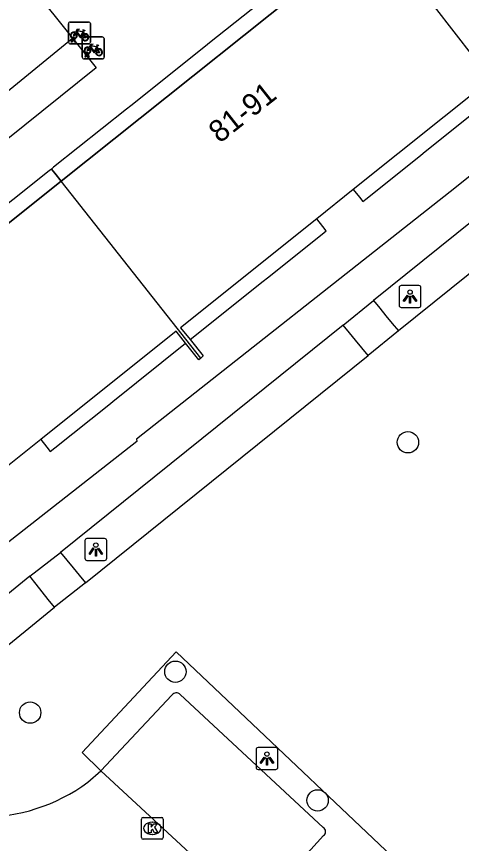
# Model space of a CAD drawing. Extents: x 159040 to 160094, y 381214 to 382518.
# Drawn here: x 159691.35 to 159711.7, y 381820.24 to 381858.06 of the extents above; entities that cross this region are included whole.
import ezdxf

# ---------------------------------------------------------------- set-up
doc = ezdxf.new("R2010")
doc.units = 0
for name, color, linetype in [('IMGEO_Boom', 7, 'Continuous'), ('IMGEO_Fietsenrek', 7, 'Continuous'), ('IMGEO_Haag', 7, 'Continuous'), ('IMGEO_Kolk', 7, 'Continuous'), ('IMGEO_Lichtpunt', 7, 'Continuous'), ('IMGEO_Pand', 7, 'Continuous'), ('IMGEO_Pand_nummerreeks', 7, 'Continuous'), ('IMGEO_Pand_overbouw', 7, 'Continuous'), ('IMGEO_Parkeervlak_open', 7, 'Continuous'), ('IMGEO_Rijbaan_lokaal_open', 7, 'Continuous'), ('IMGEO_Voetpad_gesloten', 7, 'Continuous'), ('IMGEO_Voetpad_open', 7, 'Continuous')]:
    doc.layers.add(name, color=color, linetype=linetype)

msp = doc.modelspace()

# ---------------------------------------------------------------- linework, layer by layer
at = {"layer": 'IMGEO_Boom'}
for centre in [(159709.248, 381838.586), (159698.615, 381828.091), (159691.971, 381826.221), (159705.119, 381822.205)]:
    msp.add_circle(centre, 0.489, dxfattribs=at)
at = {"layer": 'IMGEO_Fietsenrek'}
for p, q in [((159693.725, 381856.883), (159693.725, 381857.724)), ((159693.725, 381857.724), (159693.725, 381856.883)), ((159693.8, 381857.808), (159694.641, 381857.808)), ((159694.641, 381857.808), (159693.8, 381857.808)), ((159694.725, 381857.733), (159694.725, 381856.892)), ((159694.725, 381856.892), (159694.725, 381857.733)), ((159694.412, 381857.357), (159694.448, 381857.262)), ((159694.65, 381856.808), (159693.809, 381856.808)), ((159693.809, 381856.808), (159694.65, 381856.808)), ((159693.852, 381856.892), (159693.891, 381857.052)), ((159693.886, 381856.892), (159693.852, 381856.892)), ((159693.921, 381857.04), (159693.886, 381856.892)), ((159693.963, 381857.064), (159693.962, 381857.068)), ((159694.004, 381856.892), (159693.97, 381857.034)), ((159693.994, 381857.075), (159693.995, 381857.068)), ((159694.002, 381857.038), (159694.037, 381856.892)), ((159694.037, 381856.892), (159694.004, 381856.892)), ((159694.354, 381856.198), (159694.354, 381857.039)), ((159694.354, 381857.039), (159694.354, 381856.198)), ((159694.429, 381857.123), (159695.27, 381857.123)), ((159695.27, 381857.123), (159694.429, 381857.123)), ((159695.354, 381857.048), (159695.354, 381856.207)), ((159695.354, 381856.207), (159695.354, 381857.048)), ((159695.041, 381856.672), (159695.077, 381856.577)), ((159695.279, 381856.123), (159694.438, 381856.123)), ((159694.438, 381856.123), (159695.279, 381856.123)), ((159694.481, 381856.207), (159694.52, 381856.367)), ((159694.515, 381856.207), (159694.481, 381856.207)), ((159694.55, 381856.355), (159694.515, 381856.207)), ((159694.592, 381856.379), (159694.591, 381856.383)), ((159694.633, 381856.207), (159694.599, 381856.349)), ((159694.623, 381856.39), (159694.624, 381856.383)), ((159694.631, 381856.353), (159694.666, 381856.207)), ((159694.666, 381856.207), (159694.633, 381856.207))]:
    msp.add_line(p, q, dxfattribs=at)
for points in [[(159694.059, 381857.282), (159694.007, 381857.192), (159693.967, 381857.167), (159693.968, 381857.214), (159694.023, 381857.308)], [(159694.038, 381857.334), (159694.133, 381857.498), (159694.219, 381857.484), (159694.221, 381857.475), (159694.165, 381857.464), (159694.138, 381857.419), (159694.394, 381857.378)], [(159694.334, 381857.09), (159694.284, 381857.09), (159694.093, 381857.341), (159694.074, 381857.309)], [(159694.381, 381857.353), (159694.124, 381857.394), (159694.107, 381857.365), (159694.274, 381857.145), (159694.381, 381857.353)], [(159694.429, 381857.255), (159694.399, 381857.332), (159694.29, 381857.114), (159694.333, 381857.114)], [(159694.363, 381857.114), (159694.483, 381857.113), (159694.439, 381857.227)], [(159694.459, 381857.234), (159694.514, 381857.089), (159694.364, 381857.089)], [(159694.394, 381857.378), (159694.419, 381857.427), (159694.413, 381857.431), (159694.39, 381857.435), (159694.378, 381857.442), (159694.377, 381857.445), (159694.379, 381857.45), (159694.474, 381857.435), (159694.476, 381857.425), (159694.466, 381857.412), (159694.454, 381857.406), (159694.44, 381857.412), (159694.412, 381857.357)], [(159694.667, 381856.649), (159694.762, 381856.813), (159694.848, 381856.799), (159694.85, 381856.79), (159694.794, 381856.779), (159694.767, 381856.734), (159695.023, 381856.693)], [(159694.688, 381856.597), (159694.636, 381856.507), (159694.596, 381856.482), (159694.597, 381856.529), (159694.652, 381856.623)], [(159694.963, 381856.405), (159694.913, 381856.405), (159694.722, 381856.656), (159694.703, 381856.624)], [(159695.01, 381856.668), (159694.753, 381856.709), (159694.736, 381856.68), (159694.903, 381856.46), (159695.01, 381856.668)], [(159695.058, 381856.57), (159695.028, 381856.647), (159694.919, 381856.429), (159694.962, 381856.429)], [(159694.992, 381856.429), (159695.112, 381856.428), (159695.068, 381856.542)], [(159695.088, 381856.549), (159695.143, 381856.404), (159694.993, 381856.404)], [(159695.023, 381856.693), (159695.048, 381856.742), (159695.042, 381856.746), (159695.019, 381856.75), (159695.007, 381856.757), (159695.006, 381856.76), (159695.008, 381856.765), (159695.103, 381856.75), (159695.105, 381856.74), (159695.095, 381856.727), (159695.083, 381856.721), (159695.069, 381856.727), (159695.041, 381856.672)]]:
    msp.add_lwpolyline(points, dxfattribs=at)
for centre, radius, start, end in [((159693.803, 381857.73), 0.0779, 92.4484, 184.2845), ((159693.803, 381857.73), 0.0779, 92.4484, 184.2845), ((159694.647, 381857.73), 0.0779, 2.4484, 94.2845), ((159694.647, 381857.73), 0.0779, 2.4484, 94.2845), ((159693.965, 381857.193), 0.159, 62.6766, 242.1369), ((159693.965, 381857.193), 0.129, 63.3192, 238.903), ((159693.965, 381857.193), 0.129, 283.6043, 43.4302), ((159693.965, 381857.193), 0.159, 283.5766, 46.6042), ((159694.492, 381857.109), 0.159, 113.3408, 178.3217), ((159694.492, 381857.109), 0.159, 187.0065, 105.7708), ((159694.492, 381857.109), 0.129, 113.923, 177.9556), ((159694.492, 381857.109), 0.129, 188.6715, 104.5883), ((159693.803, 381856.886), 0.0779, 182.4484, 274.2845), ((159693.803, 381856.886), 0.0779, 182.4484, 274.2845), ((159693.945, 381857.064), 0.0499, 12.8025, 158.6934), ((159693.965, 381857.193), 0.159, 253.9967, 271.7867), ((159693.945, 381857.064), 0.0174, 12.8025, 163.4502), ((159693.965, 381857.193), 0.129, 253.415, 269.0204), ((159694.432, 381857.045), 0.0779, 92.4484, 184.2845), ((159694.432, 381857.045), 0.0779, 92.4484, 184.2845), ((159694.647, 381856.886), 0.0779, 272.4484, 4.2845), ((159694.647, 381856.886), 0.0779, 272.4484, 4.2845), ((159695.276, 381857.045), 0.0779, 2.4484, 94.2845), ((159695.276, 381857.045), 0.0779, 2.4484, 94.2845), ((159694.594, 381856.508), 0.159, 62.6766, 242.1369), ((159694.594, 381856.508), 0.129, 63.3192, 238.903), ((159694.574, 381856.379), 0.0499, 12.8025, 158.6934), ((159694.594, 381856.508), 0.129, 283.6043, 43.4302), ((159694.594, 381856.508), 0.159, 283.5766, 46.6042), ((159695.121, 381856.424), 0.159, 113.3408, 178.3217), ((159695.121, 381856.424), 0.159, 187.0065, 105.7708), ((159695.121, 381856.424), 0.129, 113.923, 177.9556), ((159695.121, 381856.424), 0.129, 188.6715, 104.5883), ((159694.432, 381856.201), 0.0779, 182.4484, 274.2845), ((159694.432, 381856.201), 0.0779, 182.4484, 274.2845), ((159694.594, 381856.508), 0.159, 253.9967, 271.7867), ((159694.574, 381856.379), 0.0174, 12.8025, 163.4502), ((159694.594, 381856.508), 0.129, 253.415, 269.0204), ((159695.276, 381856.201), 0.0779, 272.4484, 4.2845), ((159695.276, 381856.201), 0.0779, 272.4484, 4.2845)]:
    msp.add_arc(centre, radius, start, end, dxfattribs=at)
at = {"layer": 'IMGEO_Haag'}
for points in [[(159683.256, 381848.357), (159693.903, 381857.065)], [(159721.644, 381853.983), (159708.82, 381843.677)], [(159694.506, 381832.155), (159707.427, 381842.553)], [(159684.126, 381823.723), (159693.082, 381831.042)], [(159695.21, 381823.556), (159694.347, 381824.39), (159698.652, 381828.997), (159711.13, 381817.175)]]:
    msp.add_lwpolyline(points, dxfattribs=at)
at = {"layer": 'IMGEO_Kolk'}
for p, q in [((159697.06, 381820.502), (159697.06, 381821.354)), ((159697.135, 381821.428), (159697.987, 381821.428)), ((159698.061, 381821.354), (159698.061, 381820.502)), ((159697.548, 381821.208), (159697.573, 381821.208)), ((159697.571, 381820.648), (159697.546, 381820.648)), ((159697.987, 381820.428), (159697.135, 381820.428))]:
    msp.add_line(p, q, dxfattribs=at)
for points in [[(159697.06, 381820.502), (159697.06, 381821.354)], [(159697.135, 381821.428), (159697.987, 381821.428)], [(159698.061, 381821.354), (159698.061, 381820.502)], [(159697.381, 381821.128), (159697.504, 381821.128), (159697.504, 381820.977), (159697.634, 381821.128), (159697.798, 381821.128), (159697.652, 381820.977), (159697.805, 381820.728), (159697.653, 381820.728), (159697.568, 381820.892), (159697.504, 381820.825), (159697.504, 381820.728), (159697.381, 381820.728), (159697.381, 381821.128)], [(159697.987, 381820.428), (159697.135, 381820.428)]]:
    msp.add_lwpolyline(points, dxfattribs=at)
for centre, start, end in [((159697.137, 381821.352), 91.552, 178.448), ((159697.137, 381821.352), 91.552, 178.448), ((159697.985, 381821.352), 1.552, 88.448), ((159697.985, 381821.352), 1.552, 88.448), ((159697.137, 381820.504), 181.552, 268.448), ((159697.137, 381820.504), 181.552, 268.448), ((159697.985, 381820.504), 271.552, 358.448), ((159697.985, 381820.504), 271.552, 358.448)]:
    msp.add_arc(centre, 0.0765, start, end, dxfattribs=at)
for centre, major_axis, ratio, start_param, end_param in [((159697.547, 381820.928), (-0.387, 0.002), 0.722429, 4.712389, 7.853982), ((159697.572, 381820.928), (-0.39, 0.002), 0.717154, 1.570796, 4.712389)]:
    msp.add_ellipse(centre, major_axis=major_axis, ratio=ratio, start_param=start_param, end_param=end_param, dxfattribs=at)
at = {"layer": 'IMGEO_Lichtpunt'}
for p, q in [((159708.85, 381845.654), (159708.85, 381844.847)), ((159708.85, 381845.654), (159708.85, 381844.847)), ((159709.752, 381845.749), (159708.944, 381845.749)), ((159709.752, 381845.749), (159708.944, 381845.749)), ((159709.846, 381844.847), (159709.846, 381845.654)), ((159709.846, 381844.847), (159709.846, 381845.654)), ((159708.944, 381844.753), (159709.752, 381844.753)), ((159708.944, 381844.753), (159709.752, 381844.753)), ((159694.476, 381834.086), (159694.476, 381833.279)), ((159694.476, 381834.086), (159694.476, 381833.279)), ((159695.378, 381834.181), (159694.57, 381834.181)), ((159695.378, 381834.181), (159694.57, 381834.181)), ((159695.472, 381833.279), (159695.472, 381834.086)), ((159695.472, 381833.279), (159695.472, 381834.086)), ((159694.57, 381833.185), (159695.378, 381833.185)), ((159694.57, 381833.185), (159695.378, 381833.185)), ((159702.303, 381824.525), (159702.303, 381823.718)), ((159702.303, 381824.525), (159702.303, 381823.718)), ((159703.205, 381824.62), (159702.397, 381824.62)), ((159703.205, 381824.62), (159702.397, 381824.62)), ((159703.299, 381823.718), (159703.299, 381824.525)), ((159703.299, 381823.718), (159703.299, 381824.525)), ((159702.397, 381823.624), (159703.205, 381823.624)), ((159702.397, 381823.624), (159703.205, 381823.624))]:
    msp.add_line(p, q, dxfattribs=at)
for points in [[(159709.224, 381845.318), (159709.263, 381845.29), (159709.075, 381845.028), (159709.037, 381845.055), (159709.224, 381845.318)], [(159709.326, 381845.27), (159709.373, 381845.27), (159709.373, 381844.948), (159709.326, 381844.948), (159709.326, 381845.27)], [(159709.436, 381845.29), (159709.474, 381845.317), (159709.661, 381845.055), (159709.622, 381845.027), (159709.436, 381845.29)], [(159694.85, 381833.75), (159694.889, 381833.722), (159694.701, 381833.46), (159694.663, 381833.487), (159694.85, 381833.75)], [(159695.062, 381833.722), (159695.1, 381833.749), (159695.287, 381833.487), (159695.248, 381833.459), (159695.062, 381833.722)], [(159694.952, 381833.702), (159694.999, 381833.702), (159694.999, 381833.38), (159694.952, 381833.38), (159694.952, 381833.702)], [(159702.677, 381824.189), (159702.716, 381824.161), (159702.528, 381823.899), (159702.49, 381823.926), (159702.677, 381824.189)], [(159702.779, 381824.141), (159702.826, 381824.141), (159702.826, 381823.819), (159702.779, 381823.819), (159702.779, 381824.141)], [(159702.889, 381824.161), (159702.927, 381824.188), (159703.114, 381823.926), (159703.075, 381823.898), (159702.889, 381824.161)]]:
    msp.add_lwpolyline(points, dxfattribs=at)
for centre in [(159709.349, 381845.452), (159694.975, 381833.884), (159702.802, 381824.323)]:
    msp.add_circle(centre, 0.0994, dxfattribs=at)
for centre, start, end in [((159708.944, 381845.654), 90, 180), ((159708.944, 381845.654), 90, 180), ((159709.752, 381845.654), 0, 90), ((159709.752, 381845.654), 0, 90), ((159708.944, 381844.847), 180, 270), ((159708.944, 381844.847), 180, 270), ((159709.752, 381844.847), 270, 0), ((159709.752, 381844.847), 270, 360), ((159694.57, 381834.086), 90, 180), ((159694.57, 381834.086), 90, 180), ((159695.378, 381834.086), 0, 90), ((159695.378, 381834.086), 0, 90), ((159694.57, 381833.279), 180, 270), ((159694.57, 381833.279), 180, 270), ((159695.378, 381833.279), 270, 0), ((159695.378, 381833.279), 270, 360), ((159702.397, 381824.525), 90, 180), ((159702.397, 381824.525), 90, 180), ((159703.205, 381824.525), 0, 90), ((159703.205, 381824.525), 0, 90), ((159702.397, 381823.718), 180, 270), ((159702.397, 381823.718), 180, 270), ((159703.205, 381823.718), 270, 0), ((159703.205, 381823.718), 270, 360)]:
    msp.add_arc(centre, 0.0946, start, end, dxfattribs=at)
at = {"layer": 'IMGEO_Pand'}
for points in [[(159707.762, 381862.012), (159693.382, 381850.53)], [(159714.07, 381853.886), (159707.762, 381862.012)], [(159714.07, 381853.886), (159713.971, 381853.805), (159713.378, 381854.553), (159712.946, 381855.097), (159706.749, 381850.14), (159705.078, 381848.804), (159698.849, 381843.822), (159699.289, 381843.279), (159699.891, 381842.534), (159699.779, 381842.44)], [(159693.382, 381850.53), (159679.099, 381839.125), (159678.67, 381839.678), (159678.435, 381839.496)], [(159699.779, 381842.44), (159693.382, 381850.53)], [(159699.779, 381842.44), (159699.684, 381842.362), (159699.083, 381843.115), (159698.642, 381843.667), (159692.456, 381838.715), (159690.777, 381837.369), (159684.522, 381832.36), (159684.96, 381831.814), (159684.855, 381831.73), (159684.725, 381831.626), (159678.435, 381839.496)]]:
    msp.add_lwpolyline(points, dxfattribs=at)
at = {"layer": 'IMGEO_Pand_overbouw'}
for points in [[(159707.762, 381862.012), (159707.483, 381862.371), (159707.33, 381862.569), (159707.144, 381862.421), (159703.805, 381859.755), (159703.616, 381859.604), (159700.179, 381856.86), (159699.984, 381856.705), (159696.57, 381853.979), (159696.371, 381853.821), (159693.046, 381851.167), (159692.943, 381851.084), (159693.099, 381850.888), (159693.382, 381850.53)], [(159713.378, 381854.553), (159712.946, 381855.097), (159706.749, 381850.14), (159707.031, 381849.79), (159707.187, 381849.594), (159707.381, 381849.749), (159709.845, 381851.723), (159710.041, 381851.879)], [(159678.67, 381839.678), (159679.099, 381839.125), (159693.382, 381850.53), (159693.099, 381850.888), (159692.943, 381851.084), (159692.847, 381851.008), (159689.507, 381848.341), (159689.308, 381848.182), (159685.882, 381845.447), (159685.682, 381845.287), (159682.27, 381842.563), (159682.066, 381842.401)], [(159705.078, 381848.804), (159698.849, 381843.822), (159699.289, 381843.279), (159702.635, 381845.952), (159702.826, 381846.105), (159705.326, 381848.103), (159705.516, 381848.255), (159705.36, 381848.45)], [(159699.083, 381843.115), (159698.642, 381843.667), (159692.456, 381838.715), (159692.737, 381838.363), (159692.893, 381838.168), (159693.092, 381838.326), (159695.566, 381840.303), (159695.759, 381840.458)]]:
    msp.add_lwpolyline(points, close=True, dxfattribs=at)
at = {"layer": 'IMGEO_Parkeervlak_open'}
for points in [[(159698.456, 381827.026), (159695.21, 381823.556)], [(159705.379, 381820.963), (159698.835, 381827.044)], [(159702.488, 381817.401), (159705.394, 381820.597)]]:
    msp.add_lwpolyline(points, dxfattribs=at)
for centre, radius, start, end in [((159698.653, 381826.883), 0.243, 41.4133, 144.025), ((159705.268, 381820.775), 0.218, 305.2812, 59.4126)]:
    msp.add_arc(centre, radius, start, end, dxfattribs=at)
at = {"layer": 'IMGEO_Rijbaan_lokaal_open'}
for points in [[(159694.616, 381823.046), (159695.21, 381823.556)], [(159695.21, 381823.556), (159702.524, 381816.79)]]:
    msp.add_lwpolyline(points, dxfattribs=at)
msp.add_arc((159689.745, 381829.603), 8.168, 232.5883, 306.6076, dxfattribs=at)
at = {"layer": 'IMGEO_Voetpad_gesloten'}
for points in [[(159759.91, 381838.199), (159731.741, 381864.255), (159729.111, 381864.371), (159711.176, 381850.04), (159696.84, 381838.731), (159696.855, 381838.62), (159689.775, 381833.087), (159686.085, 381829.985)], [(159720.515, 381855.386), (159707.672, 381845.07)], [(159706.29, 381843.941), (159707.672, 381845.07)], [(159706.29, 381843.941), (159693.362, 381833.546)], [(159691.958, 381832.457), (159693.362, 381833.546)], [(159691.958, 381832.457), (159687.165, 381828.558)]]:
    msp.add_lwpolyline(points, dxfattribs=at)
at = {"layer": 'IMGEO_Voetpad_open'}
for points in [[(159690.142, 381861.769), (159693.903, 381857.065)], [(159693.903, 381857.065), (159694.985, 381855.71), (159684.261, 381847.1), (159683.256, 381848.357)], [(159707.672, 381845.07), (159707.961, 381844.719), (159708.247, 381844.371), (159708.534, 381844.024), (159708.82, 381843.677)], [(159707.427, 381842.553), (159707.142, 381842.901), (159706.857, 381843.249), (159706.571, 381843.597), (159706.29, 381843.941)], [(159708.82, 381843.677), (159707.427, 381842.553)], [(159693.362, 381833.546), (159693.648, 381833.197), (159693.934, 381832.85), (159694.22, 381832.502), (159694.506, 381832.155)], [(159693.082, 381831.042), (159692.802, 381831.394), (159692.522, 381831.747), (159692.242, 381832.099), (159691.958, 381832.457)], [(159694.506, 381832.155), (159693.082, 381831.042)]]:
    msp.add_lwpolyline(points, dxfattribs=at)

# ---------------------------------------------------------------- texts
at = {"layer": 'IMGEO_Pand_nummerreeks'}
msp.add_text('81-91', height=1, rotation=38.3332, dxfattribs=at).set_placement((159700.638, 381852.233))

doc.saveas('drawing.dxf')
